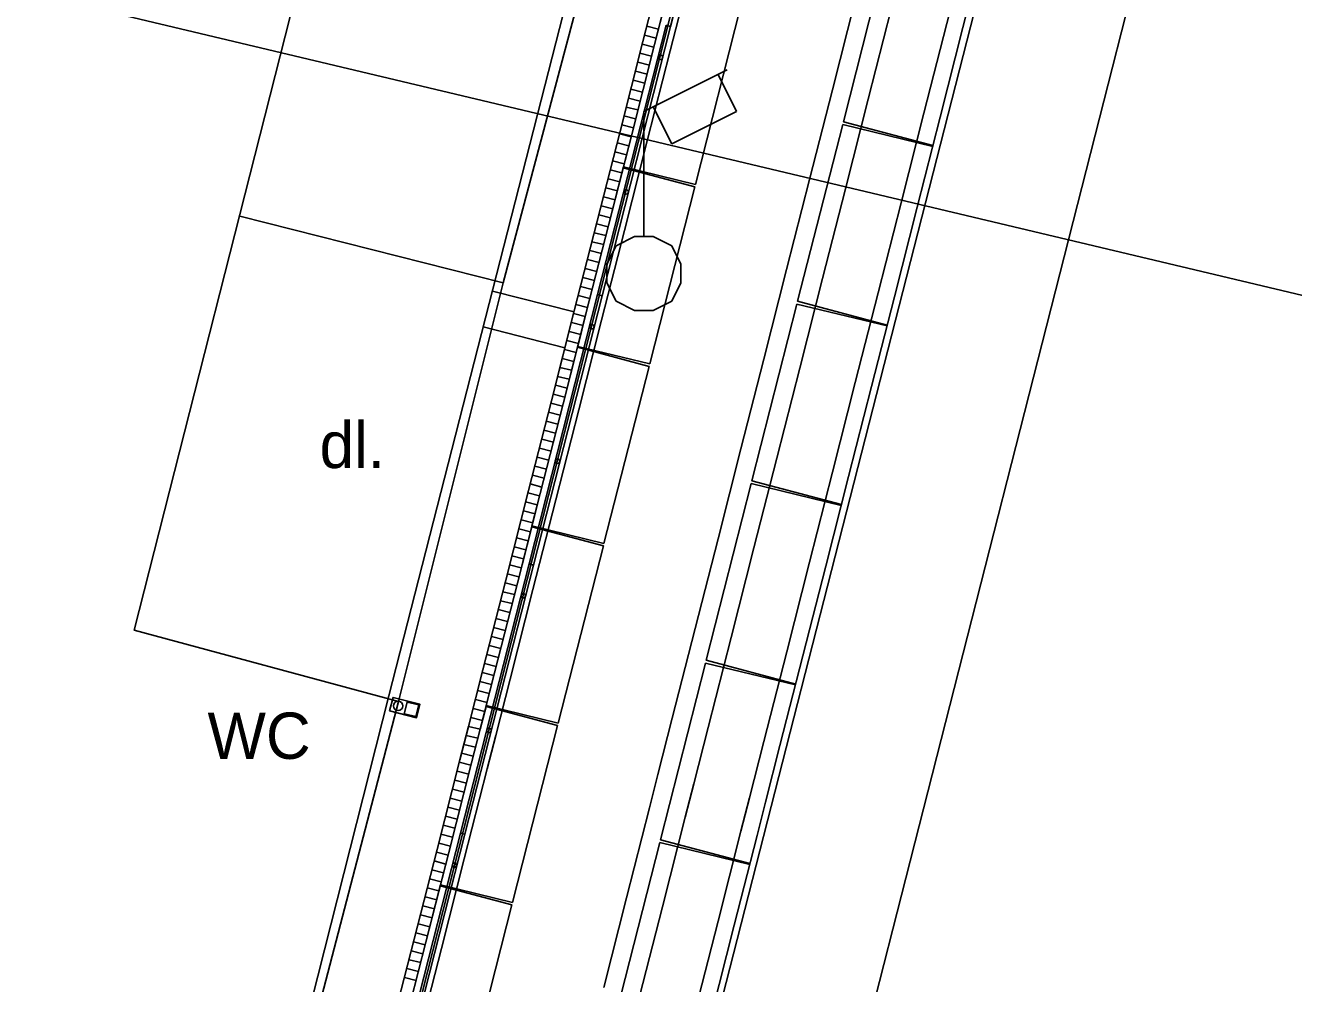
# Model space of a CAD drawing. Extents: x -733601 to -733291, y -1137892 to -1137187.
# Drawn here: x -733465.26 to -733451.57, y -1137682.75 to -1137672.4 of the extents above; entities that cross this region are included whole.
import ezdxf

# ---------------------------------------------------------------- set-up
doc = ezdxf.new("R2010")
doc.units = 0
for name, color, linetype in [('Rozvrzeni', 7, 'Continuous'), ('SIT_PUV_BUS', 7, 'Continuous'), ('SIT_PUV_ZELEZNICE', 7, 'Continuous')]:
    doc.layers.add(name, color=color, linetype=linetype)

msp = doc.modelspace()

# ---------------------------------------------------------------- linework, layer by layer
at = {"layer": 'Rozvrzeni'}
msp.add_lwpolyline([(-733564.934, -1137648.317), (-733492.008, -1137341.875), (-733347.542, -1137376.254), (-733420.468, -1137682.696)], close=True, dxfattribs=at)
at = {"layer": 'SIT_PUV_BUS'}
for p, q in [((-733456.56, -1137649.32), (-733464.08, -1137678.93)), ((-733453.45, -1137650.19), (-733460.1, -1137675.18)), ((-733455.27, -1137660.37), (-733460.18, -1137679.73)), ((-733452.43, -1137662.15), (-733466.53, -1137717.32)), ((-733458.58, -1137673.33), (-733457.68, -1137672.88)), ((-733457.78, -1137672.93), (-733457.58, -1137673.33)), ((-733458.28, -1137673.68), (-733458.48, -1137673.28)), ((-733458.58, -1137674.68), (-733458.58, -1137673.33)), ((-733457.58, -1137673.33), (-733458.28, -1137673.68)), ((-733460.1, -1137675.18), (-733462.94, -1137674.46)), ((-733458.98, -1137674.98), (-733458.88, -1137674.78)), ((-733458.88, -1137674.78), (-733458.68, -1137674.68)), ((-733458.68, -1137674.68), (-733458.48, -1137674.68)), ((-733458.48, -1137674.68), (-733458.28, -1137674.78)), ((-733458.28, -1137674.78), (-733458.18, -1137674.98)), ((-733458.98, -1137675.18), (-733458.98, -1137674.98)), ((-733458.18, -1137674.98), (-733458.18, -1137675.18)), ((-733461.23, -1137679.7), (-733460.1, -1137675.18)), ((-733458.88, -1137675.38), (-733458.98, -1137675.18)), ((-733458.18, -1137675.18), (-733458.28, -1137675.38)), ((-733458.68, -1137675.48), (-733458.88, -1137675.38)), ((-733458.28, -1137675.38), (-733458.48, -1137675.48)), ((-733458.48, -1137675.48), (-733458.68, -1137675.48)), ((-733464.08, -1137678.93), (-733461.23, -1137679.7)), ((-733461.23, -1137679.7), (-733462.88, -1137686.05)), ((-733460.18, -1137679.73), (-733469.47, -1137716.2))]:
    msp.add_line(p, q, dxfattribs=at)
at = {"layer": 'SIT_PUV_ZELEZNICE'}
for p, q in [((-733458.291, -1137672.412), (-733457.551, -1137669.505)), ((-733455.941, -1137671.533), (-733456.427, -1137673.442)), ((-733457.536, -1137672.205), (-733458.023, -1137674.118)), ((-733459.079, -1137675.308), (-733458.338, -1137672.4)), ((-733459.032, -1137675.32), (-733458.291, -1137672.412)), ((-733458.422, -1137672.442), (-733458.548, -1137672.41)), ((-733458.338, -1137672.4), (-733458.291, -1137672.412)), ((-733458.291, -1137672.412), (-733458.338, -1137672.4)), ((-733458.447, -1137672.539), (-733458.572, -1137672.507)), ((-733458.496, -1137672.733), (-733458.622, -1137672.701)), ((-733458.471, -1137672.636), (-733458.597, -1137672.604)), ((-733458.521, -1137672.83), (-733458.647, -1137672.798)), ((-733458.57, -1137673.024), (-733458.696, -1137672.992)), ((-733458.545, -1137672.927), (-733458.671, -1137672.895)), ((-733458.595, -1137673.121), (-733458.721, -1137673.089)), ((-733458.644, -1137673.314), (-733458.77, -1137673.282)), ((-733458.619, -1137673.218), (-733458.745, -1137673.185)), ((-733458.669, -1137673.411), (-733458.795, -1137673.379)), ((-733458.693, -1137673.508), (-733458.819, -1137673.476)), ((-733456.434, -1137673.471), (-733456.921, -1137675.38)), ((-733455.463, -1137673.708), (-733456.434, -1137673.471)), ((-733456.427, -1137673.442), (-733455.46, -1137673.698)), ((-733458.743, -1137673.702), (-733458.869, -1137673.67)), ((-733458.718, -1137673.605), (-733458.844, -1137673.573)), ((-733458.767, -1137673.799), (-733458.893, -1137673.767)), ((-733458.817, -1137673.993), (-733458.943, -1137673.961)), ((-733458.792, -1137673.896), (-733458.918, -1137673.864)), ((-733458.803, -1137673.938), (-733458.03, -1137674.144)), ((-733458.023, -1137674.118), (-733458.8, -1137673.929)), ((-733458.841, -1137674.09), (-733458.967, -1137674.058)), ((-733458.866, -1137674.187), (-733458.992, -1137674.155)), ((-733458.03, -1137674.144), (-733458.517, -1137676.056)), ((-733458.916, -1137674.38), (-733459.042, -1137674.348)), ((-733458.891, -1137674.284), (-733459.017, -1137674.251)), ((-733458.94, -1137674.477), (-733459.066, -1137674.445)), ((-733458.99, -1137674.671), (-733459.116, -1137674.639)), ((-733458.965, -1137674.574), (-733459.091, -1137674.542)), ((-733459.014, -1137674.768), (-733459.14, -1137674.736)), ((-733459.039, -1137674.865), (-733459.165, -1137674.833)), ((-733459.088, -1137675.059), (-733459.214, -1137675.027)), ((-733459.064, -1137674.962), (-733459.19, -1137674.93)), ((-733459.113, -1137675.156), (-733459.239, -1137675.124)), ((-733459.333, -1137675.493), (-733460.215, -1137675.269)), ((-733459.819, -1137678.215), (-733459.079, -1137675.308)), ((-733459.772, -1137678.227), (-733459.032, -1137675.32)), ((-733459.162, -1137675.35), (-733459.288, -1137675.317)), ((-733459.138, -1137675.253), (-733459.264, -1137675.221)), ((-733459.079, -1137675.308), (-733459.032, -1137675.32)), ((-733459.032, -1137675.32), (-733459.079, -1137675.308)), ((-733459.187, -1137675.446), (-733459.313, -1137675.414)), ((-733456.928, -1137675.409), (-733457.414, -1137677.318)), ((-733455.956, -1137675.646), (-733456.928, -1137675.409)), ((-733456.921, -1137675.38), (-733455.954, -1137675.636)), ((-733459.236, -1137675.64), (-733459.362, -1137675.608)), ((-733459.212, -1137675.543), (-733459.338, -1137675.511)), ((-733460.314, -1137675.656), (-733459.432, -1137675.881)), ((-733459.261, -1137675.737), (-733459.387, -1137675.705)), ((-733459.286, -1137675.834), (-733459.412, -1137675.802)), ((-733459.297, -1137675.876), (-733458.523, -1137676.082)), ((-733458.517, -1137676.056), (-733459.294, -1137675.867)), ((-733459.335, -1137676.028), (-733459.461, -1137675.996)), ((-733459.311, -1137675.931), (-733459.436, -1137675.899)), ((-733459.36, -1137676.125), (-733459.486, -1137676.093)), ((-733458.523, -1137676.082), (-733459.011, -1137677.995)), ((-733459.409, -1137676.319), (-733459.535, -1137676.286)), ((-733459.385, -1137676.222), (-733459.511, -1137676.19)), ((-733459.434, -1137676.415), (-733459.56, -1137676.383)), ((-733459.459, -1137676.512), (-733459.585, -1137676.48)), ((-733459.508, -1137676.706), (-733459.634, -1137676.674)), ((-733459.483, -1137676.609), (-733459.609, -1137676.577)), ((-733459.533, -1137676.803), (-733459.659, -1137676.771)), ((-733459.582, -1137676.997), (-733459.708, -1137676.965)), ((-733459.557, -1137676.9), (-733459.683, -1137676.868)), ((-733459.607, -1137677.094), (-733459.733, -1137677.062)), ((-733459.631, -1137677.191), (-733459.757, -1137677.159)), ((-733459.681, -1137677.385), (-733459.807, -1137677.352)), ((-733459.656, -1137677.288), (-733459.782, -1137677.256)), ((-733457.422, -1137677.347), (-733457.908, -1137679.256)), ((-733456.45, -1137677.584), (-733457.422, -1137677.347)), ((-733457.414, -1137677.318), (-733456.448, -1137677.575)), ((-733459.705, -1137677.481), (-733459.831, -1137677.449)), ((-733459.755, -1137677.675), (-733459.881, -1137677.643)), ((-733459.73, -1137677.578), (-733459.856, -1137677.546)), ((-733459.78, -1137677.772), (-733459.906, -1137677.74)), ((-733459.829, -1137677.966), (-733459.955, -1137677.934)), ((-733459.804, -1137677.869), (-733459.93, -1137677.837)), ((-733459.79, -1137677.814), (-733459.017, -1137678.02)), ((-733459.011, -1137677.995), (-733459.788, -1137677.805)), ((-733459.854, -1137678.063), (-733459.98, -1137678.031)), ((-733459.017, -1137678.02), (-733459.504, -1137679.933)), ((-733459.878, -1137678.16), (-733460.004, -1137678.128)), ((-733460.56, -1137681.122), (-733459.819, -1137678.215)), ((-733460.513, -1137681.134), (-733459.772, -1137678.227)), ((-733459.928, -1137678.354), (-733460.054, -1137678.321)), ((-733459.903, -1137678.257), (-733460.029, -1137678.225)), ((-733459.819, -1137678.215), (-733459.772, -1137678.227)), ((-733459.772, -1137678.227), (-733459.819, -1137678.215)), ((-733459.952, -1137678.45), (-733460.078, -1137678.418)), ((-733460.002, -1137678.644), (-733460.128, -1137678.612)), ((-733459.977, -1137678.547), (-733460.103, -1137678.515)), ((-733460.026, -1137678.741), (-733460.152, -1137678.709)), ((-733460.051, -1137678.838), (-733460.177, -1137678.806)), ((-733460.1, -1137679.032), (-733460.226, -1137679)), ((-733460.076, -1137678.935), (-733460.202, -1137678.903)), ((-733460.125, -1137679.129), (-733460.251, -1137679.097)), ((-733460.175, -1137679.323), (-733460.3, -1137679.291)), ((-733460.15, -1137679.226), (-733460.276, -1137679.194)), ((-733457.915, -1137679.285), (-733458.402, -1137681.194)), ((-733456.944, -1137679.522), (-733457.915, -1137679.285)), ((-733457.908, -1137679.256), (-733456.941, -1137679.513)), ((-733460.199, -1137679.42), (-733460.325, -1137679.387)), ((-733460.224, -1137679.516), (-733460.35, -1137679.484)), ((-733460.273, -1137679.71), (-733460.399, -1137679.678)), ((-733460.249, -1137679.613), (-733460.375, -1137679.581)), ((-733460.298, -1137679.807), (-733460.424, -1137679.775)), ((-733460.284, -1137679.753), (-733459.511, -1137679.958)), ((-733459.504, -1137679.933), (-733460.282, -1137679.743)), ((-733460.347, -1137680.001), (-733460.473, -1137679.969)), ((-733460.323, -1137679.904), (-733460.449, -1137679.872)), ((-733459.511, -1137679.958), (-733459.998, -1137681.871)), ((-733460.372, -1137680.098), (-733460.498, -1137680.066)), ((-733460.421, -1137680.292), (-733460.547, -1137680.26)), ((-733460.397, -1137680.195), (-733460.523, -1137680.163)), ((-733460.446, -1137680.389), (-733460.572, -1137680.356)), ((-733460.471, -1137680.485), (-733460.597, -1137680.453)), ((-733460.52, -1137680.679), (-733460.646, -1137680.647)), ((-733460.495, -1137680.582), (-733460.621, -1137680.55)), ((-733460.545, -1137680.776), (-733460.671, -1137680.744)), ((-733460.594, -1137680.97), (-733460.72, -1137680.938)), ((-733460.569, -1137680.873), (-733460.695, -1137680.841)), ((-733460.619, -1137681.067), (-733460.745, -1137681.035)), ((-733461.3, -1137684.029), (-733460.56, -1137681.122)), ((-733461.254, -1137684.041), (-733460.513, -1137681.134)), ((-733460.644, -1137681.164), (-733460.77, -1137681.132)), ((-733460.56, -1137681.122), (-733460.513, -1137681.134)), ((-733460.513, -1137681.134), (-733460.56, -1137681.122)), ((-733458.402, -1137681.194), (-733457.435, -1137681.451)), ((-733460.693, -1137681.358), (-733460.819, -1137681.326)), ((-733460.668, -1137681.261), (-733460.794, -1137681.229)), ((-733458.409, -1137681.223), (-733458.895, -1137683.132)), ((-733457.438, -1137681.461), (-733458.409, -1137681.223)), ((-733460.718, -1137681.455), (-733460.844, -1137681.422)), ((-733460.767, -1137681.648), (-733460.893, -1137681.616)), ((-733460.742, -1137681.551), (-733460.868, -1137681.519)), ((-733460.792, -1137681.745), (-733460.918, -1137681.713)), ((-733460.778, -1137681.691), (-733460.004, -1137681.896)), ((-733459.998, -1137681.871), (-733460.775, -1137681.681)), ((-733460.816, -1137681.842), (-733460.942, -1137681.81)), ((-733460.004, -1137681.896), (-733460.492, -1137683.809)), ((-733460.866, -1137682.036), (-733460.992, -1137682.004)), ((-733460.841, -1137681.939), (-733460.967, -1137681.907)), ((-733460.89, -1137682.133), (-733461.016, -1137682.101)), ((-733460.94, -1137682.327), (-733461.066, -1137682.295)), ((-733460.915, -1137682.23), (-733461.041, -1137682.198)), ((-733460.964, -1137682.424), (-733461.09, -1137682.391)), ((-733461.014, -1137682.617), (-733461.14, -1137682.585)), ((-733460.989, -1137682.52), (-733461.115, -1137682.488)), ((-733461.039, -1137682.714), (-733461.164, -1137682.682))]:
    msp.add_line(p, q, dxfattribs=at)
for points in [[(-733473.591, -1137751.638), (-733472.603, -1137747.76), (-733470.135, -1137738.069), (-733467.666, -1137728.379), (-733465.198, -1137718.688), (-733462.729, -1137708.998), (-733460.26, -1137699.307), (-733457.792, -1137689.617), (-733455.323, -1137679.926), (-733452.855, -1137670.236), (-733450.386, -1137660.545), (-733448.734, -1137654.061), (-733447.917, -1137650.855), (-733445.432, -1137641.168), (-733442.928, -1137631.487), (-733440.405, -1137621.811), (-733437.862, -1137612.139), (-733437.8, -1137611.906), (-733435.314, -1137602.469), (-733432.775, -1137592.797), (-733432.613, -1137592.177)], [(-733462.935, -1137685.963), (-733461.332, -1137679.64), (-733453.759, -1137650.014), (-733456.593, -1137649.288), (-733465.899, -1137646.951)], [(-733461.011, -1137683.337), (-733460.764, -1137682.368), (-733460.518, -1137681.399), (-733460.271, -1137680.429), (-733460.179, -1137680.069), (-733460.024, -1137679.46), (-733459.777, -1137678.491), (-733459.53, -1137677.522), (-733459.283, -1137676.553), (-733459.036, -1137675.584), (-733458.789, -1137674.615), (-733458.543, -1137673.646), (-733458.296, -1137672.676), (-733458.049, -1137671.707), (-733457.802, -1137670.738), (-733457.555, -1137669.769), (-733457.308, -1137668.8), (-733457.061, -1137667.83), (-733456.814, -1137666.861), (-733456.567, -1137665.892), (-733456.32, -1137664.922), (-733456.073, -1137663.953), (-733455.827, -1137662.983), (-733455.58, -1137662.014)], [(-733461.306, -1137683.236), (-733461.059, -1137682.267), (-733460.812, -1137681.298), (-733460.565, -1137680.329), (-733460.473, -1137679.969), (-733460.318, -1137679.36), (-733460.071, -1137678.391), (-733459.825, -1137677.422), (-733459.578, -1137676.453), (-733459.331, -1137675.484), (-733459.084, -1137674.515), (-733458.837, -1137673.546), (-733458.59, -1137672.576), (-733458.343, -1137671.607), (-733458.096, -1137670.638), (-733457.849, -1137669.669), (-733457.602, -1137668.699), (-733457.356, -1137667.73), (-733457.109, -1137666.761), (-733456.862, -1137665.791), (-733456.615, -1137664.822), (-733455.965, -1137662.273)], [(-733461.18, -1137683.269), (-733460.933, -1137682.299), (-733460.686, -1137681.33), (-733460.439, -1137680.361), (-733460.347, -1137680.001), (-733460.192, -1137679.392), (-733459.945, -1137678.423), (-733459.699, -1137677.454), (-733459.452, -1137676.485), (-733459.205, -1137675.516), (-733458.958, -1137674.547), (-733458.711, -1137673.578), (-733458.464, -1137672.608), (-733458.217, -1137671.639), (-733457.97, -1137670.67), (-733457.723, -1137669.701), (-733457.477, -1137668.731), (-733457.23, -1137667.762), (-733456.983, -1137666.793), (-733456.736, -1137665.824), (-733456.489, -1137664.854), (-733455.839, -1137662.305)], [(-733459.014, -1137682.788), (-733458.767, -1137681.819), (-733458.52, -1137680.85), (-733458.429, -1137680.49), (-733458.274, -1137679.881), (-733458.027, -1137678.912), (-733457.78, -1137677.943), (-733457.533, -1137676.974), (-733457.286, -1137676.005), (-733457.039, -1137675.036), (-733456.792, -1137674.066), (-733456.545, -1137673.097), (-733456.299, -1137672.128), (-733456.052, -1137671.159), (-733455.805, -1137670.189), (-733455.558, -1137669.22), (-733455.311, -1137668.251), (-733455.064, -1137667.282), (-733454.817, -1137666.312), (-733454.57, -1137665.343), (-733454.323, -1137664.374), (-733454.076, -1137663.404), (-733453.829, -1137662.435)], [(-733458.626, -1137682.887), (-733458.38, -1137681.918), (-733458.133, -1137680.949), (-733458.041, -1137680.589), (-733457.886, -1137679.98), (-733457.639, -1137679.011), (-733457.392, -1137678.042), (-733457.145, -1137677.073), (-733456.898, -1137676.103), (-733456.652, -1137675.134), (-733456.405, -1137674.165), (-733456.158, -1137673.196), (-733455.911, -1137672.227), (-733455.664, -1137671.257), (-733455.417, -1137670.288), (-733455.17, -1137669.319), (-733454.923, -1137668.35), (-733454.676, -1137667.38), (-733454.429, -1137666.411), (-733454.182, -1137665.442), (-733453.936, -1137664.472), (-733453.689, -1137663.503), (-733453.442, -1137662.534)], [(-733458.026, -1137683.04), (-733457.779, -1137682.071), (-733457.532, -1137681.102), (-733457.44, -1137680.742), (-733457.285, -1137680.133), (-733457.038, -1137679.164), (-733456.791, -1137678.195), (-733456.545, -1137677.226), (-733456.298, -1137676.256), (-733456.051, -1137675.287), (-733455.804, -1137674.318), (-733455.557, -1137673.349), (-733455.31, -1137672.38), (-733455.063, -1137671.411), (-733454.816, -1137670.441), (-733454.569, -1137669.472), (-733454.322, -1137668.503), (-733454.076, -1137667.533), (-733453.829, -1137666.564), (-733453.582, -1137665.595), (-733453.335, -1137664.625), (-733453.088, -1137663.656), (-733452.841, -1137662.687)], [(-733457.851, -1137683.084), (-733457.604, -1137682.115), (-733457.358, -1137681.146), (-733457.266, -1137680.786), (-733457.111, -1137680.177), (-733456.864, -1137679.208), (-733456.617, -1137678.239), (-733456.37, -1137677.27), (-733456.123, -1137676.301), (-733455.876, -1137675.332), (-733455.629, -1137674.363), (-733455.383, -1137673.393), (-733455.136, -1137672.424), (-733454.889, -1137671.455), (-733454.642, -1137670.486), (-733454.395, -1137669.516), (-733454.148, -1137668.547), (-733453.901, -1137667.578), (-733453.654, -1137666.609), (-733453.407, -1137665.639), (-733453.16, -1137664.67), (-733452.913, -1137663.7), (-733452.666, -1137662.731)], [(-733458.343, -1137671.607), (-733458.59, -1137672.576), (-733458.837, -1137673.546), (-733459.084, -1137674.515), (-733459.331, -1137675.484), (-733459.396, -1137675.74), (-733459.495, -1137676.127), (-733459.578, -1137676.453), (-733459.825, -1137677.422), (-733460.071, -1137678.391), (-733460.318, -1137679.36), (-733460.473, -1137679.969), (-733460.565, -1137680.329), (-733460.812, -1137681.298), (-733461.059, -1137682.267), (-733461.306, -1137683.236)], [(-733461.18, -1137683.269), (-733460.933, -1137682.299), (-733460.778, -1137681.691), (-733460.775, -1137681.681), (-733460.686, -1137681.33), (-733460.439, -1137680.361), (-733460.347, -1137680.001), (-733460.284, -1137679.753), (-733460.282, -1137679.743), (-733460.192, -1137679.392), (-733459.945, -1137678.423), (-733459.79, -1137677.814), (-733459.788, -1137677.805), (-733459.699, -1137677.454), (-733459.452, -1137676.485), (-733459.297, -1137675.876), (-733459.294, -1137675.867), (-733459.205, -1137675.516), (-733458.958, -1137674.547), (-733458.803, -1137673.938), (-733458.8, -1137673.929), (-733458.711, -1137673.578), (-733458.464, -1137672.608), (-733458.309, -1137672)]]:
    msp.add_lwpolyline(points, dxfattribs=at)
for points in [[(-733461.324, -1137679.802), (-733461.287, -1137679.657), (-733460.997, -1137679.731), (-733461.033, -1137679.876)], [(-733461.167, -1137679.832), (-733461.135, -1137679.706), (-733461.009, -1137679.738), (-733461.041, -1137679.864)]]:
    msp.add_lwpolyline(points, close=True, dxfattribs=at)
for centre, radius in [((-733458.401, -1137672.746), 0.0241), ((-733458.771, -1137674.199), 0.0241), ((-733459.142, -1137675.653), 0.0241), ((-733459.512, -1137677.106), 0.0241), ((-733459.882, -1137678.56), 0.0241), ((-733461.233, -1137679.748), 0.05), ((-733460.252, -1137680.013), 0.0241), ((-733460.623, -1137681.467), 0.0241)]:
    msp.add_circle(centre, radius, dxfattribs=at)

# ---------------------------------------------------------------- texts
at = {"layer": 'SIT_PUV_BUS'}
for s, p in [('dl.', (-733462.08, -1137677.18)), ('WC', (-733463.29, -1137680.32))]:
    msp.add_text(s, height=0.5, dxfattribs=at).set_placement(p)

doc.saveas('drawing.dxf')
